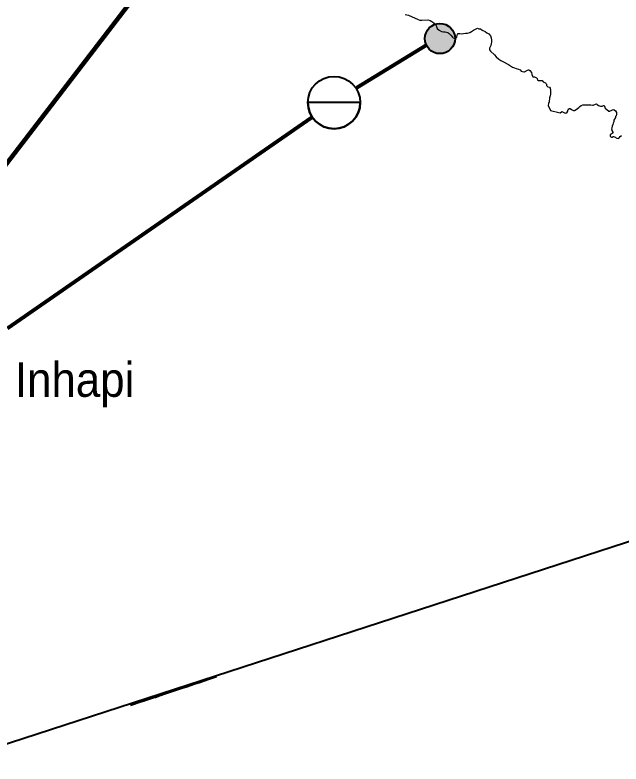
# Model space of a CAD drawing. Extents: x 553962 to 842807, y 8883888 to 9032388.
# Drawn here: x 637550 to 646335, y 8974784 to 8985636 of the extents above; entities that cross this region are included whole.
import ezdxf

# ---------------------------------------------------------------- set-up
doc = ezdxf.new("R2010")
doc.units = 0
doc.header["$LTSCALE"] = 200
for name, color, linetype, lineweight in [('12', 7, 'Continuous', 25), ('24', 7, 'Continuous', 25), ('28', 7, 'Continuous', 40), ('41', 7, 'Continuous', 40), ('9', 7, 'Continuous', 90)]:
    doc.layers.add(name, color=color, linetype=linetype, lineweight=lineweight)

msp = doc.modelspace()

# ---------------------------------------------------------------- hatches: boundary and pattern name
at = {"layer": '41'}
msp.add_hatch(color=256, dxfattribs=at).paths.add_polyline_path([(643928.5, 8985294.1, 1), (643490.8, 8985294.1, 1)])

# ---------------------------------------------------------------- linework, layer by layer
at = {"layer": '12', "lineweight": 40}
msp.add_line((636526.5, 8974783.6), (662912, 8983353), dxfattribs=at)
for points in [[(640472.4, 8976046.8), (640441.5, 8976036.8), (640353.5, 8976006.1), (640287.6, 8975985.5), (640218.7, 8975961.9), (640200.9, 8975957.3), (640150.5, 8975938.5), (640099.3, 8975922.4), (640029.6, 8975897.5), (639963, 8975876.6), (639893.2, 8975851.7), (639703, 8975789.1)], [(639703, 8975789.1), (639664.1, 8975776.3), (639645.5, 8975769.1), (639623.8, 8975762.9), (639586.7, 8975748.7), (639556.7, 8975741.9), (639455.8, 8975707.4), (639444.1, 8975705), (639415.3, 8975694.5), (639380.3, 8975685.2), (639226.1, 8975631.6)]]:
    msp.add_lwpolyline(points, dxfattribs=at)
at = {"layer": '24'}
for points in [[(643204.1, 8985642.6), (643255.2, 8985632.2), (643391.8, 8985570.3), (643419.6, 8985560.6), (643448.3, 8985559.2), (643535.1, 8985564.4), (643566.8, 8985554.4), (643593.8, 8985539.8), (643620, 8985522.8), (643645.8, 8985498.4), (643661.8, 8985469), (643671.2, 8985440.6), (643696.1, 8985416.2), (643730.8, 8985396.7), (643760.5, 8985389.3), (643787.3, 8985391.9), (643824.7, 8985383.8), (643827.6, 8985378.5), (643844.2, 8985367.4), (643865.5, 8985345.4), (643891.9, 8985312.7), (643902.2, 8985304.6), (643918.1, 8985298.3), (643931.2, 8985298.1), (643942, 8985300.2), (643956, 8985315.2), (643958.1, 8985343.4), (643962.6, 8985351.1), (643974.6, 8985365.4), (643986.6, 8985368.4), (643998.1, 8985366.4), (644024.1, 8985364.5), (644080, 8985371.7), (644110.9, 8985373), (644143.4, 8985382.5), (644168.5, 8985396.6), (644196.1, 8985417.2), (644224.2, 8985431.8), (644254, 8985444.8), (644273.9, 8985433.2), (644296.8, 8985435.6), (644322.2, 8985414.2), (644363.5, 8985395.3), (644391.1, 8985376.3), (644419.5, 8985362.5), (644442.3, 8985331.1), (644453.3, 8985302.5), (644457.5, 8985272.5), (644457.4, 8985247.7), (644454.2, 8985219.9), (644448.7, 8985192.2), (644431.3, 8985165), (644427.1, 8985155.8), (644427.3, 8985131.1), (644442.3, 8985109.9), (644498.8, 8985056.6), (644525.5, 8985029), (644563, 8984997.2), (644593.4, 8984976), (644619.6, 8984960.8), (644704.7, 8984916.9), (644762.1, 8984880.9), (644788.2, 8984867.8), (644814.3, 8984857.8), (644846.8, 8984850.4), (644871.5, 8984838.7), (644888.1, 8984823.5), (644924.3, 8984813.9), (644936.7, 8984813.3), (644980.1, 8984838.3), (644995.5, 8984839.8), (644999.2, 8984838.9), (645011.4, 8984829.6), (645036.6, 8984800.8), (645040, 8984774.7), (645055.3, 8984741.8), (645079.3, 8984738.2), (645111, 8984727.2), (645116.6, 8984716.9), (645122.7, 8984692.8), (645125.9, 8984690.1), (645134.7, 8984687.1), (645179, 8984687.9), (645191.9, 8984684.7), (645204.7, 8984665), (645215.6, 8984660.4), (645240.1, 8984653.1), (645246.2, 8984645.1)], [(645246.2, 8984645.1), (645252, 8984633.7), (645252, 8984633.7), (645252.8, 8984617.9), (645254.9, 8984614.1), (645273, 8984596.3), (645297.8, 8984587.5), (645307.1, 8984577.2), (645309.6, 8984572.6), (645313.5, 8984545.7), (645310.3, 8984489.1), (645306.1, 8984462.2), (645298.7, 8984433.5), (645293.2, 8984378.7), (645284.9, 8984350.8), (645279.8, 8984323.9), (645312.4, 8984251.8), (645435.1, 8984220.4), (645450.8, 8984217.4), (645454.7, 8984218.6), (645473, 8984232.8), (645474.4, 8984237.7), (645513, 8984217.7), (645534.3, 8984215.3), (645552.1, 8984228.2), (645561.4, 8984244.2), (645563.4, 8984257.6), (645571, 8984266.9), (645573.8, 8984274.1), (645582.1, 8984275.2), (645588.9, 8984280.3), (645595.8, 8984280.6), (645617.2, 8984264.5), (645643.7, 8984251.2), (645657.8, 8984251.3), (645685.7, 8984265.8), (645720.8, 8984294.7), (645739.3, 8984311.6), (645757.9, 8984321.9), (645781.4, 8984331.5), (645806.7, 8984335.8), (645852, 8984333.8), (645898.3, 8984333.7), (645921.8, 8984328.7), (645932, 8984328.5), (645966, 8984344.7), (645976.9, 8984346.4), (645987.8, 8984340.9), (646010.2, 8984326), (646036.9, 8984314.5), (646055.1, 8984312.7), (646060.6, 8984315.8), (646079.4, 8984322.4), (646090.5, 8984322.5), (646097, 8984312.2), (646105.3, 8984283.1), (646157.1, 8984243.2), (646170.2, 8984242.8), (646179.3, 8984244.7), (646193.2, 8984252.7), (646210.9, 8984260.5), (646231.3, 8984263.8), (646234.4, 8984263.1), (646256, 8984249.2), (646271.1, 8984222.9), (646271.2, 8984198.1), (646264.8, 8984175), (646256.7, 8984163.4), (646252.5, 8984152.3), (646232.4, 8984111.9), (646228.6, 8984089.8), (646221.2, 8984067.5), (646217.8, 8984047), (646208.5, 8984025.5), (646201.6, 8984002.4), (646197.2, 8983982.5), (646199.9, 8983977.5), (646203.5, 8983960.5), (646214.4, 8983938.6), (646218.5, 8983926.6), (646208.4, 8983916.5), (646177.6, 8983897.5), (646174.8, 8983879.2), (646187.6, 8983870.2), (646196.7, 8983867.3), (646206, 8983867.2), (646221.1, 8983872.7), (646226.9, 8983872.9), (646242.3, 8983868.7), (646272.1, 8983849.4), (646291.4, 8983848.2), (646301.4, 8983851.2), (646309, 8983856.7), (646323, 8983874.5), (646341.7, 8983889.2)]]:
    msp.add_lwpolyline(points, dxfattribs=at)
at = {"layer": '28', "lineweight": 80}
for p, q in [((642506.2, 8984582.9), (643524.1, 8985208.9)), ((637441.9, 8981098.3), (641847.2, 8984152.4))]:
    msp.add_line(p, q, dxfattribs=at)
at = {"layer": '28'}
msp.add_line((642553.9, 8984365.9), (641795.1, 8984365.9), dxfattribs=at)
msp.add_circle((642174.5, 8984365.9), 379.4, dxfattribs=at)
msp.add_arc((642174.5, 8984365.9), 379.4, 180, 0, dxfattribs=at)
at = {"layer": '41'}
msp.add_circle((643709.6, 8985294.1), 218.8, dxfattribs=at)
at = {"layer": '9'}
msp.add_lwpolyline([(635350.7, 8977923.9), (636116.8, 8981777.4), (642228, 8989744.8), (647160.3, 8990514), (649828, 8995545.6), (655722.5, 9001435.5), (661506.7, 9009120.3)], dxfattribs=at)

# ---------------------------------------------------------------- texts
at = {"layer": '41', "width": 0.95}
msp.add_text('Inhapi', height=500, dxfattribs=at).set_placement((637549, 8980103.2))
msp.add_text('Inhapi', height=500, dxfattribs=at).set_placement((637549, 8980103.2))

doc.saveas('drawing.dxf')
